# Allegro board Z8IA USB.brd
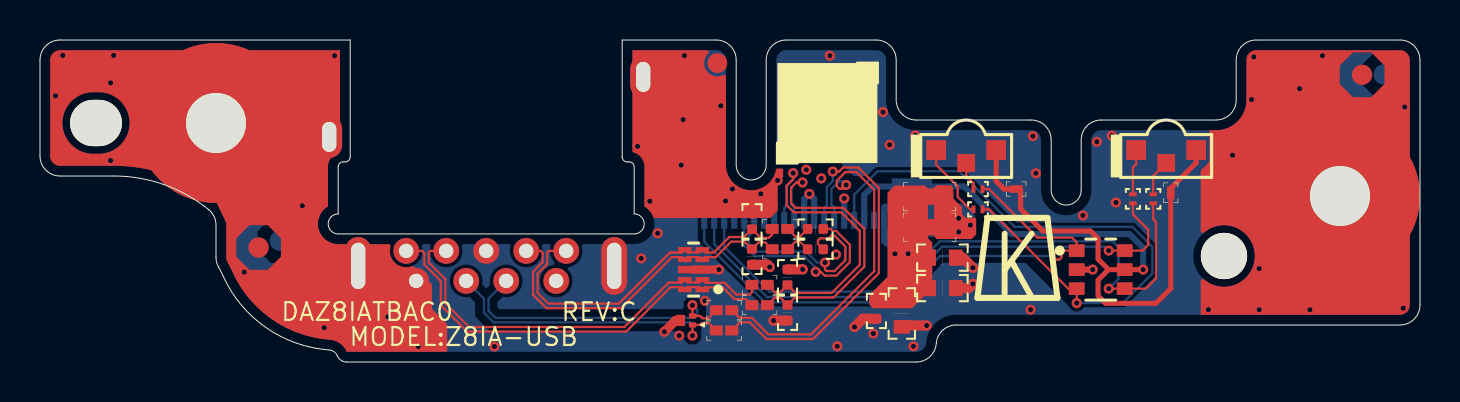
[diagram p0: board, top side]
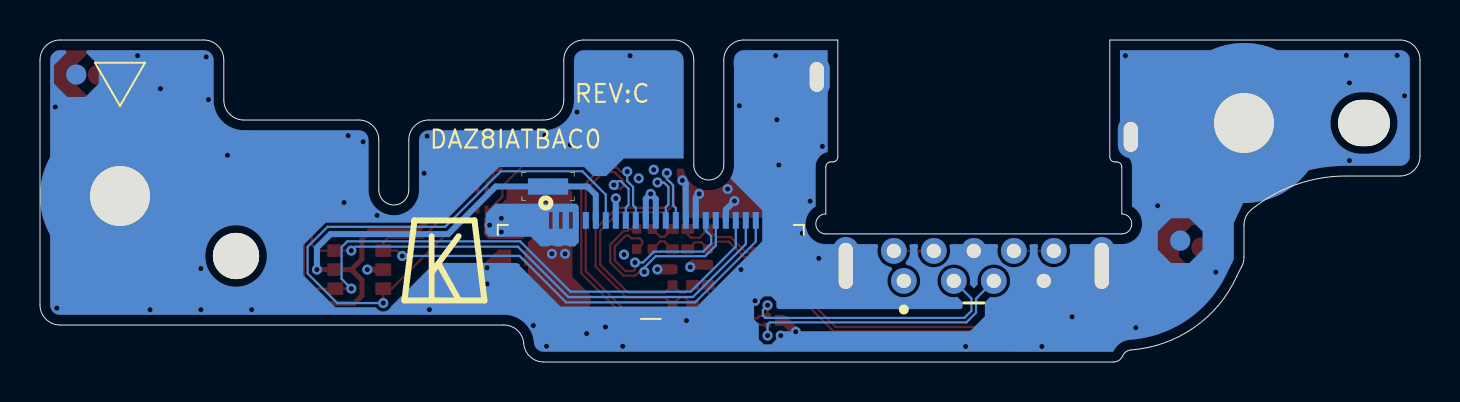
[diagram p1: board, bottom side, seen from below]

Outline 69 x 16.1 mm; copper layers: TOP, SGND, IN1, SVCC, IN2, IN3, SGND1, IN4, SGND2, BOTTOM. Coordinates in mm from the lower left corner of the outline.
Outline path: 0,15.1 0,10.3 arc(0.29,9.59) 1,9.3 3.7,9.3 arc(6.21,8.87) 8.43,7.62 arc(8.7,7.27) 8.8,6.84 8.8,5.23 arc(8.83,4.98) 8.93,4.74 arc(9.05,4.52) 9.16,4.29 arc(11.3,1.72) 14.45,0.6 arc(14.7,0.51) 14.87,0.3 arc(15.05,0.08) 15.33,0 43.82,0 arc(44.5,0.27) 44.81,0.92 arc(45.13,1.58) 45.81,1.85 68,1.85 arc(68.71,2.14) 69,2.85 69,15.1 arc(68.71,15.81) 68,16.1 60.81,16.1 arc(60.1,15.81) 59.81,15.1 59.81,13.1 arc(59.52,12.39) 58.81,12.1 53.06,12.1 arc(52.35,11.81) 52.06,11.1 52.06,8.6 arc(51.31,7.85) 50.56,8.6 50.56,11.1 arc(50.27,11.81) 49.56,12.1 43.81,12.1 arc(43.1,12.39) 42.81,13.1 42.81,15.1 arc(42.52,15.81) 41.81,16.1 37.31,16.1 arc(36.6,15.81) 36.31,15.1 36.31,9.85 arc(35.56,9.1) 34.81,9.85 34.81,15.1 arc(34.52,15.81) 33.81,16.1 29.11,16.1 29.11,10.25 arc(29.18,10.08) 29.36,10 29.46,10 arc(29.64,9.93) 29.71,9.75 29.71,7.4 arc(30.21,6.9) 29.71,6.4 14.91,6.4 arc(14.41,6.9) 14.91,7.4 14.91,9.75 arc(14.98,9.93) 15.16,10 15.26,10 arc(15.44,10.08) 15.51,10.25 15.51,16.1 1,16.1 arc(0.29,15.81) 0,15.1

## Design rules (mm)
constraint set DEFAULT: min track width 0.114
net group DFP-S4.5(3.5: nets USB30_RX4+ USB30_RX4+_C USB30_RX4- USB30_RX4-_C USB30_TX4+ USB30_TX4+_C USB30_TX4+_C_R USB30_TX4- USB30_TX4-_C USB30_TX4-_C_R USBP4+_DB USBP4+_DB_R USBP4-_DB USBP4-_DB_R

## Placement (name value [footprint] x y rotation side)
C523  *1.6p/50V_4  [C0402]  37.38 2.46 270 top
C526  *1.6p/50V_4  [C0402]  37.38 4.24 90 top
C530  0.1u/16V_4  [C0402]  38.77 5.64 0 top
C531  0.1u/16V_4  [C0402]  38.77 6.65 0 top
C534  *1.6p/50V_4  [C0402]  35.6 5.26 90 top
C535  *1.6p/50V_4  [C0402]  35.6 7.03 270 top
C536  47u/6.3V_6  [C0603]  43.09 2.42 90 top
C537  47u/6.3V_6  [C0603]  45.12 3.69 180 top
C538  47u/6.3V_6  [C0603]  45.12 5.22 180 top
CN1  51540-02201-V01  [FPC-51540-02201-V01-22P-L]  38.46 3.9 180 bottom
CN2  10580-09001  [UB3-10580-09001-9P]  22.31 11.25 0 bottom
D13099  MESD05N92ULA  [DFN1006-3-1X0_6-0_55H-3P]  32.3 2.08 0 top
D13100  TVM0G5R5M261R_260p  [R0402]  41.82 2.55 90 top
ESD2  TVL_ST23_04_AD0  [SOT23-2_8-95-6P-AOZ8904]  53.04 4.62 180 top
HOLE1  *h-c91d91n  [H-C91D91N]  59.2 5.3 0 top
HOLE2  *h-o102x91d102x91n  [H-O102X91D102X91N]  2.8 11.95 0 top
HOLE3  *h-c315d118p2  [H-C315D118P2]  8.8 11.95 0 top
HOLE4  *h-c315d118p2  [H-C315D118P2]  65 8.3 0 top
LED1  Blue/Orange_LTST-S326TBKFKT-Q  [LEDLTST-S326KGJRKT-3P-SMT]  56.31 10.6 0 top
LED2  Blue/Orange_LTST-S326TBKFKT-Q  [LEDLTST-S326KGJRKT-3P-SMT]  46.31 10.6 0 top
NOREF  -  [unnamed]  10.93 5.73 0 top
NOREF#2  -  [#2]  48.88 5.2 0 top
NOREF#3  -  [unnamed]  66.11 14.36 0 top
NOREF#4  -  [#2]  -22.86 -103.72 0 top
NOREF#5  -  [unnamed#3]  39.37 12.45 180 top
NOREF#6  -  [#2]  27.94 -63.59 0 top
NOREF#7  -  [#2]  48.77 5.08 180 bottom
NOREF#8  -  [unnamed]  67.18 14.37 180 bottom
NOREF#9  -  [unnamed]  11.99 6.07 180 bottom
R3  100_1%_2  [R0201]  55.66 8.16 90 top
R4  *Short_2  [S0201]  56.54 8.46 270 top
R5  150_1%_2  [R0201]  54.65 8.16 90 top
R6  100_1%_2  [R0201]  46.9 8.65 180 top
R7  *Short_2  [S0201]  48.81 8.65 0 top
R8  150_1%_2  [R0201]  46.9 7.63 180 top
R425  *Short_4  [S0402]  34.2 1.57 0 top
R426  *Short_4  [S0402]  34.2 2.59 0 top
R427  *Short_4  [S0402]  35.98 2.84 0 top
R428  *Short_4  [S0402]  35.98 3.86 0 top
R429  *Short_4  [S0402]  37 5.64 0 top
R430  *Short_4  [S0402]  37 6.65 0 top
R68790  *Short_0603  [S0603]  43.6 8.77 180 bottom
R68791  *Short_0603  [S0603]  44.49 8.27 0 top
R68792  *Short_0603  [S0603]  44.49 6.74 0 top
U17  AZ1045-04F.R7G  [ESD10-2_5X1-5-9P-AZ1143]  32.68 4.62 90 top

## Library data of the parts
C523 C526 C530 C531 C534-C538 = CAP_NON-POL_BGM
CN1 = FFCFPC_22P_BGM
CN2 = USB3_9P_4fix_V3_BGM
D13099 = TVS_DIODE_DUAL_BGM
D13100 = VARISTOR_BGM
ESD2 = TVL_ST23_04_AD0_BGM
HOLE1-HOLE4 = 3x2_6.1
LED1 LED2 = LED_3P_Blue_OR_BGM
R3-R8 R425-R430 = RES_BGM
R68790-R68792 = SHORTPAD_V01_BGM
U17 = AZ1045-04F_BGM

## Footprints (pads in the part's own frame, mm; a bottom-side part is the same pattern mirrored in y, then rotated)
C0402
  custom 0.12x0.12 smd: 1(0.39,0) 2(-0.39,0)
C0603
  rect 0.686x0.813 smd: 1(0.6,0) 2(-0.6,0)
DFN1006-3-1X0_6-0_55H-3P
  rect 0.356x0.254 smd: 1(0.325,0.225) 2(0.325,-0.225)
  rect 0.457x0.559 smd: 3(-0.275,0)
ESD10-2_5X1-5-9P-AZ1143
  rect 0.254x0.686 smd: 1(-1,-0.437) 2(-0.5,-0.437) 4(0.5,-0.437) 5(1,-0.437) 6(1,0.437) 7(0.5,0.437) 9(-0.5,0.437) 10(-1,0.437)
  rect 0.381x1.549 smd: 3(0,0)
FPC-51540-02201-V01-22P-L
  rect 0.305x0.838 smd: 1(-5.25,3.175) 2(-4.75,3.175) 3(-4.25,3.175) 4(-3.75,3.175) 5(-3.25,3.175) 6(-2.75,3.175) 7(-2.25,3.175) 8(-1.75,3.175) 9(-1.25,3.175) 10(-0.75,3.175) 11(-0.25,3.175) 12(0.25,3.175) 13(0.75,3.175) 14(1.25,3.175) 15(1.75,3.175) 16(2.25,3.175) 17(2.75,3.175) 18(3.25,3.175) 19(3.75,3.175) 20(4.25,3.175) 21(4.75,3.175) 22(5.25,3.175)
  rect 0.787x2.007 smd: 23(-6.95,0) 24(6.95,0)
H-C91D91N
  round 2.311 hole 2.311 unplated: (0,0)
H-C315D118P2
  round 8.001 hole 2.997: 1(0,0)
H-O102X91D102X91N
  oval 2.591x2.311 hole 2.591x2.311 unplated: (0,0)
LEDLTST-S326KGJRKT-3P-SMT
  rect 0.991x0.991 smd: 1(-1.5,0) 3(1.5,0)
  rect 0.889x0.889 smd: 2(0,-0.65)
R0201
  rect 0.203x0.381 smd: 1(-0.225,0) 2(0.225,0)
R0402
  custom 0.12x0.12 smd: 1(0.39,0) 2(-0.39,0)
S0201
  rect 0.343x0.381 smd: 1(-0.225,0) 2(0.225,0)
S0402
  custom 0.125x0.125 smd: 1(0.39,0) 2(-0.39,0)
S0603
  rect 1.041x0.813 smd: 1(0.6,0) 2(-0.6,0)
SOT23-2_8-95-6P-AOZ8904
  rect 0.787x0.635 smd: 1(1.2,-0.95) 2(1.2,0) 3(1.2,0.95) 4(-1.2,0.95) 5(-1.2,0) 6(-1.2,-0.95)
UB3-10580-09001-9P
  round 1.295 hole 0.711: 1(3.5,7.2) 2(1,7.2) 3(-1,7.2) 4(-3.5,7.2) 5(-4,5.7) 6(-2,5.7) 7(0,5.7) 8(2,5.7) 9(4,5.7)
  oval 1.295x2.896 hole 0.711x2.311: 10(6.4,6.45) 11(-6.4,6.45)
  oval 1.295x2.108 hole 0.711x1.499: 12(-7.85,0) 13(7.85,-3)
unnamed
  round 1.016 smd: 1(0,0)
unnamed#3
  round 0.991 smd: (5.5,-2.5)

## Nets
+3VPCU: ESD2.5(VDD) R4.2 R7.2 R68790.2
+3VPCU_BATTERY: LED2.3 R7.1
+3VPCU_POWER: LED1.3 R4.1
GND: C523.1 C526.1 C534.2 C535.2 C536.2 C537.2 C538.2 CN1.8 CN1.11 CN1.12 CN1.15 CN1.16 CN1.19 CN1.23 CN1.24 CN2.4 CN2.7 CN2.10 CN2.11 CN2.12 CN2.13 D13099.3 D13100.2 ESD2.2 HOLE3.1 HOLE4.1 U17.3
+USBPWR: C536.1 C537.1 C538.1 CN2.1(VBUS) D13100.1 R68791.2 R68792.2
BATLED0#: CN1.22 ESD2.1 R6.1
BATLED1#: CN1.7 ESD2.3 R8.1
PWRLED#: CN1.20 ESD2.4 R3.1
SUSLED#: CN1.21 ESD2.6 R5.1
USB30_RX4+: C526.2 CN1.14 R428.1
USB30_RX4+_C: CN2.6 R428.2 U17.2 U17.9
USB30_RX4-: C523.2 CN1.13 R427.1
USB30_RX4-_C: CN2.5 R427.2 U17.1 U17.10(NC#4)
USB30_TX4+: C531.1 CN1.18
USB30_TX4+_C: C531.2 R430.1
USB30_TX4+_C_R: C535.1 CN2.9 R430.2 U17.5 U17.6
USB30_TX4-: C530.1 CN1.17
USB30_TX4-_C: C530.2 R429.1
USB30_TX4-_C_R: C534.1 CN2.8 R429.2 U17.4 U17.7
USBP4+_DB: CN1.10 R425.1
USBP4+_DB_R: CN2.3 D13099.2 R425.2
USBP4-_DB: CN1.9 R426.1
USBP4-_DB_R: CN2.2 D13099.1 R426.2
N38543443: CN1.1 CN1.2 CN1.3 CN1.4 R68791.1 R68792.1
N38543463: CN1.6 R68790.1
N38547350: LED1.2 R3.2
N38547380: LED1.1(ORA) R5.2
N38547440: LED2.2 R6.2
N38547468: LED2.1(ORA) R8.2

Pads without a net: CN1 5; NOREF 1; NOREF#3 1; NOREF#8 1; NOREF#9 1

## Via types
v1: diameter 0.508, hole 0.254, TOP to BOTTOM, 84 vias

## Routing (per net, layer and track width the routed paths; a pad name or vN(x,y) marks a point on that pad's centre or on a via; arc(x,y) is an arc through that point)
+3VPCU: length 32.5
  TOP w0.254: R7.2 49.03,7.66 50.14,6.55 52.51,6.55 52.9,6.16 52.9,5.15 53.43,4.62 ; R4.2 56.54,3.68 55.79,2.93 53.28,2.93 52.9,3.31 52.9,4.09 53.43,4.62 ; 53.43,4.62 ESD2.5 v1(55.16,4.62)
  BOTTOM w0.305: R68790.2 46.21,8.77 48.59,6.4 54.47,6.4 55.16,5.71 v1(55.16,4.62)
+3VPCU_BATTERY: length 2.5
  TOP w0.254: R7.1 48.2,8.65 47.81,9.04 LED2.3
+3VPCU_POWER: length 2.4
  TOP w0.254: R4.1 57.81,9.96 LED1.3
GND: length 24.4
  TOP w0.305: ESD2.2 v1(52.64,4.62)
  TOP w0.406: U17.3 v1(33.95,4.62)
  TOP w0.457: D13099.3 31.78,2.08 v1(31.22,1.51)
  TOP w0.508: C538.2 46.14,5.22 v1(46.65,4.71) ; C537.2 46.44,3.69 v1(46.65,3.9) ; C526.1 v1(38.13,4.63) ; C534.2 36.37,4.87 v1(36.49,4.75) ; v1(34.62,8.65) 35.6,7.67 C535.2 ; D13100.2 41.14,2.16 v1(40.73,1.75) ; C523.1 v1(36.68,2.07) ; C536.2 v1(44.33,1.82)
  BOTTOM w0.305: CN1.15 36.71,8.91 v1(36.88,9.08) ; v1(40.21,8.18) CN1.8 ; CN1.19 34.71,7.62 v1(34.28,8.05) ; CN1.12 38.21,8.15 v1(38.47,8.41) 38.71,8.16 CN1.11 ; v1(36.04,8.41) 36.21,8.24 CN1.16
  BOTTOM w0.508: v1(46.65,3.9) CN1.23 ; v1(30.89,6.44) 31.51,5.81 CN1.24
  vias: v1(0.77,13.31) v1(1.14,15.33) v1(3.53,13.96) v1(3.53,10.07) v1(3.68,15.33) v1(10.21,4.5) v1(13.12,7.81) v1(14.21,1.71) v1(14.73,15.32) v1(17.4,2.26) v1(18.91,0.77) v1(22.72,0.77) v1(29.88,10.78) v1(30.06,5.18) v1(30.49,8.04) v1(31.96,1.32) v1(32.06,9.85) v1(32.22,15.32) v1(32.16,12.12) v1(33.25,3.06) v1(34.03,12.81) v1(38.31,9.61) v1(39.06,9.18) v1(39.5,15.32) v1(39.8,5.37) v1(39.86,0.79) v1(41.67,1.42) v1(42.15,12.5) v1(42.48,10.86) v1(43.67,0.79) v1(43.76,11.33) v1(49.53,2.62) v1(49.64,11.29) v1(49.8,9.44) v1(52.15,7.33) v1(52.84,11.01) v1(53.59,11.32) v1(53.8,7.97) v1(58.42,2.62) v1(59.63,10.34) v1(60.58,13.12) v1(60.69,15.25) v1(60.96,4.67) v1(60.96,2.62) v1(62.98,13.66) v1(63.5,2.62) v1(64.12,15.32) v1(68.24,12.75) v1(68.16,2.69)
+USBPWR:
  vias: v1(42.75,5.41) v1(43.41,5.41)
BATLED0#: length 28.2
  TOP w0.114: v1(50.89,5.3) 51.15,5.57 ESD2.1 51.84,5.98 51.6,6.22 49.88,6.22 47.45,8.65 R6.1
  BOTTOM w0.114: v1(50.89,5.3) 45.02,5.3 42.7,2.98 36.24,2.98 33.21,6.01 CN1.22
BATLED1#: length 31.1
  TOP w0.114: R8.1 47.45,7.63 51.41,3.67 ESD2.3 v1(51.84,2.95)
  BOTTOM w0.114: CN1.7 40.71,8.37 41.88,9.54 45.96,9.54 48.74,6.76 54.62,6.76 55.62,5.76 55.62,4.43 54.14,2.95 v1(51.84,2.95)
PWRLED#: length 31.8
  TOP w0.114: v1(53.44,3.67) ESD2.4 55.3,3.67 55.8,4.18 55.8,7 55.66,7.14 R3.1
  BOTTOM w0.114: v1(53.44,3.67) 53.92,4.16 53.92,5.74 53.63,6.03 44.99,6.03 42.47,3.52 36.46,3.52 34.21,5.77 CN1.20
SUSLED#: length 27.6
  TOP w0.114: v1(53.44,5.57) ESD2.6 55.13,5.57 55.41,5.85 55.41,6.62 54.65,7.38 R5.1
  BOTTOM w0.114: CN1.21 33.71,5.89 36.35,3.25 42.59,3.25 45.1,5.77 53.24,5.77 v1(53.44,5.57)
USB30_RX4+: length 15.9
  TOP w0.114: v1(37.66,9.45) 37.66,9.13 37.32,8.8 37.32,7.85 37.7,7.48 40.07,7.48 40.99,6.57 40.99,4.86 39.58,3.45 37.77,3.45 C526.2 36.99,3.47 36.76,3.47 R428.1
  BOTTOM w0.114: v1(37.66,9.45) 37.66,9.16 37.35,8.85 37.35,7.84 37.21,7.7 CN1.14
USB30_RX4+_C: length 21.4
  TOP w0.114: R428.2 35.59,3.48 35.49,3.38 34.81,3.38 34.23,3.96 33.27,3.96 U17.2 32.97,3.97 32.39,3.97 U17.9 32.09,3.97 31.44,3.97 29.22,1.75 21.45,1.75 20.27,2.93 20.27,4.14 19.44,4.97 19.44,5.48 19.51,5.55 CN2.6
USB30_RX4-: length 15.9
  TOP w0.114: R427.1 36.77,3.24 36.99,3.24 C523.2 37.75,3.23 39.68,3.23 41.22,4.76 41.22,6.66 40.17,7.71 37.79,7.71 37.55,7.95 37.55,8.71 37.81,8.97 37.83,8.97 37.84,8.98 v1(38.13,8.98)
  BOTTOM w0.114: v1(38.13,8.98) 37.8,8.98 37.58,8.75 37.58,7.86 37.71,7.73 CN1.13
USB30_RX4-_C: length 21.5
  TOP w0.114: R427.2 35.29,3.15 34.72,3.15 34.13,3.73 33.23,3.73 U17.1 32.99,3.75 32.37,3.75 U17.10 32.12,3.74 31.53,3.74 29.31,1.52 21.35,1.52 20.04,2.83 20.04,4.04 19.21,4.87 19.21,5.45 19.11,5.55 CN2.5
USB30_TX4+: length 10.1
  TOP w0.114: C531.1 39.52,6.65 39.62,6.55 39.81,6.55 40.49,5.87 40.49,4.99 39.82,4.32 39.24,4.32 39.05,4.51 v1(38.78,4.51)
  BOTTOM w0.114: CN1.18 35.21,5.82 35.74,5.29 38.21,5.29 38.78,4.72 v1(38.78,4.51)
USB30_TX4+_C: length 1.3
  TOP w0.114: C531.2 37.99,6.26 37.78,6.26 R430.1
USB30_TX4+_C_R: length 17.5
  TOP w0.114: CN2.9 25.44,5.55 25.36,5.48 25.36,4.9 24.88,4.42 24.88,3.46 25.42,2.92 28.94,2.92 31.5,5.47 32.09,5.47 U17.6 32.39,5.47 32.97,5.47 U17.5 33.26,5.47 33.69,5.47 34.47,6.25 35.2,6.25 C535.1 36.03,6.21 36.44,6.21 36.61,6.37 R430.2
USB30_TX4-: length 10
  TOP w0.114: v1(39.25,4.97) 39.25,4.63 39.33,4.55 39.72,4.55 40.26,5.09 40.26,5.77 39.71,6.32 39.57,6.32 39.43,6.18 39.01,6.18 38.89,6.07 38.89,5.91 C530.1
  BOTTOM w0.114: CN1.17 35.71,6.56 35.44,6.29 35.44,5.92 35.84,5.52 38.3,5.52 38.85,4.97 v1(39.25,4.97)
USB30_TX4-_C: length 1.3
  TOP w0.114: C530.2 37.99,6.03 37.78,6.03 R429.1
USB30_TX4-_C_R: length 17.4
  TOP w0.114: R429.2 36.26,5.98 35.94,5.98 C534.1 35.23,6.02 34.56,6.02 33.79,5.24 33.24,5.24 U17.4 32.99,5.24 32.36,5.24 U17.7 32.12,5.24 31.59,5.24 29.04,2.69 25.33,2.69 24.65,3.36 24.65,4.51 25.13,4.99 25.13,5.45 25.03,5.55 CN2.8
USBP4+_DB: length 18.9
  TOP w0.114: v1(39.64,9.52) 39.95,9.52 40.16,9.73 40.91,9.73 41.94,8.7 41.94,4.44 38.65,1.15 36.32,1.15 35.49,1.98 35,1.98 R425.1
  BOTTOM w0.114: v1(39.64,9.52) 39.64,9.05 39.34,8.75 39.34,7.84 39.21,7.7 CN1.10
USBP4+_DB_R: length 15.1
  TOP w0.114: R425.2 33.43,1.96 33.1,1.96 33,1.86 D13099.2 v1(32.62,1.32)
  BOTTOM w0.114: CN2.3 22.2,3.17 22.2,2.46 22.68,1.98 32.52,1.98 32.62,1.88 v1(32.62,1.32)
USBP4-_DB: length 18.9
  TOP w0.114: v1(40.31,8.85) 40.13,8.67 39.96,8.67 39.84,8.79 39.84,9.06 40.27,9.5 40.82,9.5 41.71,8.61 41.71,4.54 38.55,1.38 36.41,1.38 35.58,2.21 34.97,2.21 R426.1
  BOTTOM w0.114: CN1.9 39.71,7.72 39.57,7.86 39.57,8.65 39.96,9.04 40.12,9.04 v1(40.31,8.85)
USBP4-_DB_R: length 15
  TOP w0.114: v1(32.62,2.84) D13099.1 33,2.31 33.13,2.18 33.41,2.18 R426.2
  BOTTOM w0.114: CN2.2 22.43,3.17 22.43,2.56 22.78,2.21 32.74,2.21 32.86,2.32 32.86,2.61 v1(32.62,2.84)
N38543443:
  vias: v1(45.93,7.19) v1(45.93,6.5) v1(46.52,6.84)
N38543463: length 3.2
  BOTTOM w0.305: CN1.6 41.21,8.36 41.63,8.77 R68790.1
N38547350: length 1.8
  TOP w0.114: LED1.2 55.66,9.3 R3.2
N38547380: length 2.3
  TOP w0.114: R5.2 54.65,9.73 54.81,9.89 LED1.1
N38547440: length 1.5
  TOP w0.114: R6.2 46.68,8.95 46.31,9.31 LED2.2
N38547468: length 3.8
  TOP w0.114: R8.2 46.51,7.63 45.88,8.26 45.88,8.78 44.81,9.86 LED2.1

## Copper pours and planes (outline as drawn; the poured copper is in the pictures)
GND on TOP (solid shape): 33.33,15.59 33.43,15.53 33.41,15.42 33.26,15.2 33.21,14.95 33.4,14.48 33.87,14.28 34.02,14.3 34.16,14.35 34.25,14.34 34.3,14.26 34.3,9.85 35.44,8.6 36.8,9.62 36.8,9.64 36.84,9.68 37.12,9.68 37.16,9.64 37.16,9.25 36.89,8.98 36.89,7.57 36.51,7.2 30.68,7.2 30.5,7.53 30.22,7.78 30.22,9.75 30.06,10.22 29.66,10.49 29.62,10.5 29.62,15.59
GND on TOP (solid shape): outline of 163 points within 58.04,2.36 68.49,15.59
GND on TOP (solid shape): outline of 290 points within 0.51,0.51 20.36,15.59
GND on BOTTOM (solid shape): outline of 1093 points within 0.51,0.51 68.49,15.59
GND on SGND (solid shape): outline of 661 points within 0.51,0.51 68.49,15.59
GND on IN1 (solid shape): outline of 1799 points within 0.51,0.51 68.49,15.59
GND on SVCC (solid shape): outline of 661 points within 0.51,0.51 68.49,15.59
GND on IN2 (solid shape): outline of 1500 points within 0.51,0.51 68.49,15.59
GND on IN3 (solid shape): outline of 1799 points within 0.51,0.51 68.49,15.59
GND on SGND1 (solid shape): outline of 662 points within 0.51,0.51 68.49,15.59
GND on IN4 (solid shape): outline of 1795 points within 0.51,0.51 68.49,15.59
GND on SGND2 (solid shape): outline of 661 points within 0.51,0.51 68.49,15.59
+USBPWR on TOP (solid shape): 44.4,8.67 44.4,6.2 44.61,5.98 44.61,3.69 43.6,2.68 41.65,2.68 41.46,2.87 41.46,3.34 42.38,4.26 42.38,8.47 42.73,8.83 44.25,8.83
+USBPWR on IN2 (solid shape): outline of 349 points within 24.64,1.1 44.28,6.62
N38543443 on TOP (solid shape): 45.66,8.72 45.66,8.5 45.67,8.48 45.67,8.17 46.1,7.74 46.1,7.48 46.18,7.29 46.37,7.22 46.65,7.22 46.69,7.22 46.78,7.2 46.81,7.12 46.81,6.37 46.58,6.15 44.84,6.15 44.7,6.29 44.7,8.71 44.83,8.84 45.53,8.84
N38543443 on BOTTOM (solid shape): 46.72,7.42 46.72,6.44 46.54,6.26 44.45,6.26 43.97,5.77 43.62,5.77 43.59,5.79 43.54,5.81 43.49,5.82 43.44,5.83 43.38,5.83 43.33,5.82 43.27,5.81 43.22,5.79 43.2,5.77 42.96,5.77 42.93,5.79 42.88,5.81 42.83,5.82 42.77,5.83 42.72,5.83 42.67,5.82 42.61,5.81 42.56,5.79 42.54,5.77 42.26,5.77 42.06,5.98 42.06,6.66 43.56,6.66 43.56,7.5 43.36,7.5 43.36,6.66 43.06,6.66 43.06,7.5 42.86,7.5 42.86,6.66 42.56,6.66 42.56,7.5 42.36,7.5 42.36,6.66 42.06,6.66 42.06,7.79 42.18,7.92 46.22,7.92

Small or netless copper shapes (teardrops, artwork), in the pictures only: 3 on IN1

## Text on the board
Ref Des/Silkscreen Bottom: REV:C | DAZ8IATBAC0
User.Comments: 69 | 16.1
Ref Des/Silkscreen Top: DAZ8IATBAC0 | MODEL:Z8IA-USB | REV:C
User.45: FIGURE | SIZE | 28.0x59.0 | 28.0x91.0 | 102.0x91.0 | 10.0 | 28.0 | 118.0 | 91.0 | SLOT HOLES: TOP to BOTTOM | ALL UNITS ARE IN MILS | DRILL CHART: TOP to BOTTOM | PLATED | NON-PLATED | Rotation | 90.000 | 0.000 | - | QTY | 2 | 1 | 5 | 84 | 9 | 96 | TOTAL HOLES:
